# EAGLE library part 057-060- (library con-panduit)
CONNECTOR 60-pin series 057 contact pc board low profile headers
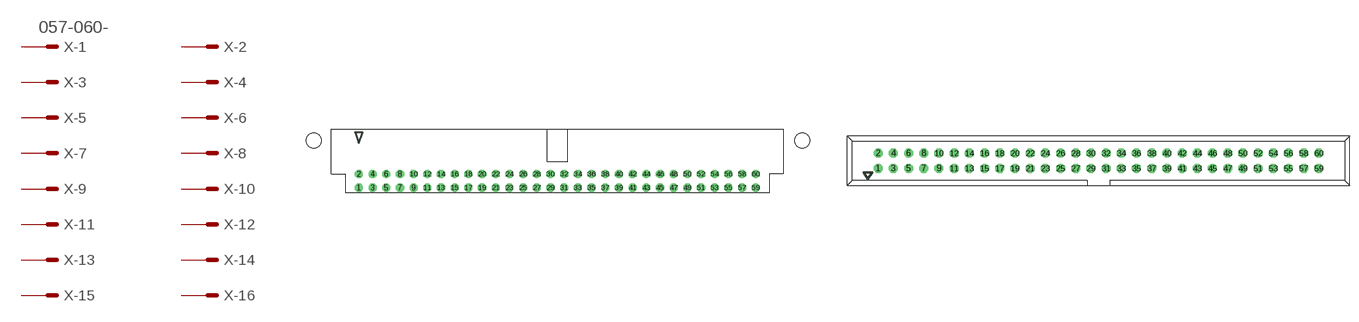
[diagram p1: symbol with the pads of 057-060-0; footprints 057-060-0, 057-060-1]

Designator prefix X; gates -1=MV -2=M -3=M -4=M -5=M -6=M -7=M -8=M -9=M -10=M -11=M -12=M -13=M -14=M -15=M -16=M -17=M -18=M -19=M -20=M -21=M -22=M -23=M -24=M -25=M -26=M -27=M -28=M -29=M -30=M -31=M -32=M -33=M -34=M -35=M -36=M -37=M -38=M -39=M -40=M -41=M -42=M -43=M -44=M -45=M -46=M -47=M -48=M -49=M -50=M -51=M -52=M -53=M -54=M -55=M -56=M -57=M -58=M -59=M -60=M

## 057-060-0 (OC_FARNELL: unknown; OC_NEWARK: unknown)  [057-060-0]
1  -1:S  pas
2  -2:S  pas
3  -3:S  pas
4  -4:S  pas
5  -5:S  pas
6  -6:S  pas
7  -7:S  pas
8  -8:S  pas
9  -9:S  pas
10  -10:S  pas
11  -11:S  pas
12  -12:S  pas
13  -13:S  pas
14  -14:S  pas
15  -15:S  pas
16  -16:S  pas
17  -17:S  pas
18  -18:S  pas
19  -19:S  pas
20  -20:S  pas
21  -21:S  pas
22  -22:S  pas
23  -23:S  pas
24  -24:S  pas
25  -25:S  pas
26  -26:S  pas
27  -27:S  pas
28  -28:S  pas
29  -29:S  pas
30  -30:S  pas
31  -31:S  pas
32  -32:S  pas
33  -33:S  pas
34  -34:S  pas
35  -35:S  pas
36  -36:S  pas
37  -37:S  pas
38  -38:S  pas
39  -39:S  pas
40  -40:S  pas
41  -41:S  pas
42  -42:S  pas
43  -43:S  pas
44  -44:S  pas
45  -45:S  pas
46  -46:S  pas
47  -47:S  pas
48  -48:S  pas
49  -49:S  pas
50  -50:S  pas
51  -51:S  pas
52  -52:S  pas
53  -53:S  pas
54  -54:S  pas
55  -55:S  pas
56  -56:S  pas
57  -57:S  pas
58  -58:S  pas
59  -59:S  pas
60  -60:S  pas

## 057-060-1 (OC_FARNELL: unknown; OC_NEWARK: unknown)  [057-060-1]
Pads as for 057-060-0

## Footprint 057-060-0 (pad centres in mm)
CONNECTOR series 057 contact pc board low profile headers angled
drill 1 octagon: 1 -36.83,-5.08; 2 -36.83,-2.54; 3 -34.29,-5.08; 4 -34.29,-2.54; 5 -31.75,-5.08; 6 -31.75,-2.54; 7 -29.21,-5.08; 8 -29.21,-2.54; 9 -26.67,-5.08; 10 -26.67,-2.54; 11 -24.13,-5.08; 12 -24.13,-2.54; 13 -21.59,-5.08; 14 -21.59,-2.54; 15 -19.05,-5.08; 16 -19.05,-2.54; 17 -16.51,-5.08; 18 -16.51,-2.54; 19 -13.97,-5.08; 20 -13.97,-2.54; 21 -11.43,-5.08; 22 -11.43,-2.54; 23 -8.89,-5.08; 24 -8.89,-2.54; 25 -6.35,-5.08; 26 -6.35,-2.54; 27 -3.81,-5.08; 28 -3.81,-2.54; 29 -1.27,-5.08; 30 -1.27,-2.54; 31 1.27,-5.08; 32 1.27,-2.54; 33 3.81,-5.08; 34 3.81,-2.54; 35 6.35,-5.08; 36 6.35,-2.54; 37 8.89,-5.08; 38 8.89,-2.54; 39 11.43,-5.08; 40 11.43,-2.54; 41 13.97,-5.08; 42 13.97,-2.54; 43 16.51,-5.08; 44 16.51,-2.54; 45 19.05,-5.08; 46 19.05,-2.54; 47 21.59,-5.08; 48 21.59,-2.54; 49 24.13,-5.08; 50 24.13,-2.54; 51 26.67,-5.08; 52 26.67,-2.54; 53 29.21,-5.08; 54 29.21,-2.54; 55 31.75,-5.08; 56 31.75,-2.54; 57 34.29,-5.08; 58 34.29,-2.54; 59 36.83,-5.08; 60 36.83,-2.54
hole 2.8 at -45.23,3.66
hole 2.8 at 45.48,3.66

## Footprint 057-060-1 (pad centres in mm)
CONNECTOR series 057 contact pc board low profile headers straight
drill 1 octagon: 1 -36.83,-1.27; 2 -36.83,1.27; 3 -34.29,-1.27; 4 -34.29,1.27; 5 -31.75,-1.27; 6 -31.75,1.27; 7 -29.21,-1.27; 8 -29.21,1.27; 9 -26.67,-1.27; 10 -26.67,1.27; 11 -24.13,-1.27; 12 -24.13,1.27; 13 -21.59,-1.27; 14 -21.59,1.27; 15 -19.05,-1.27; 16 -19.05,1.27; 17 -16.51,-1.27; 18 -16.51,1.27; 19 -13.97,-1.27; 20 -13.97,1.27; 21 -11.43,-1.27; 22 -11.43,1.27; 23 -8.89,-1.27; 24 -8.89,1.27; 25 -6.35,-1.27; 26 -6.35,1.27; 27 -3.81,-1.27; 28 -3.81,1.27; 29 -1.27,-1.27; 30 -1.27,1.27; 31 1.27,-1.27; 32 1.27,1.27; 33 3.81,-1.27; 34 3.81,1.27; 35 6.35,-1.27; 36 6.35,1.27; 37 8.89,-1.27; 38 8.89,1.27; 39 11.43,-1.27; 40 11.43,1.27; 41 13.97,-1.27; 42 13.97,1.27; 43 16.51,-1.27; 44 16.51,1.27; 45 19.05,-1.27; 46 19.05,1.27; 47 21.59,-1.27; 48 21.59,1.27; 49 24.13,-1.27; 50 24.13,1.27; 51 26.67,-1.27; 52 26.67,1.27; 53 29.21,-1.27; 54 29.21,1.27; 55 31.75,-1.27; 56 31.75,1.27; 57 34.29,-1.27; 58 34.29,1.27; 59 36.83,-1.27; 60 36.83,1.27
